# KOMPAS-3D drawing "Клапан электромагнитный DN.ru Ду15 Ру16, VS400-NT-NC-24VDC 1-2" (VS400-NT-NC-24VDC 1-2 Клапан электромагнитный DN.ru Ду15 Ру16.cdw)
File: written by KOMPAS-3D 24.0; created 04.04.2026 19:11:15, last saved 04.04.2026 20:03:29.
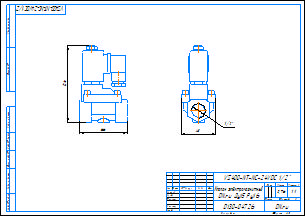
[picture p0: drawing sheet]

Document properties: c3d_UniqueCompID: ef56311e-7521-43dc-8291-0e6108b3d81d; Обозначение: VS400-ET-NC-220VAC 1-2; Наименование: Клапан электромагнитный DN.ru Ду15 Ру16; Автор: artio; Класс точности: c; Знак неуказанной шероховатости: Шероховатость не задана; Рассекать на разрезах: Да; c3d_UniqueCompID: ef56311e-7521-43dc-8291-0e6108b3d81d; Обозначение: VS400-ET-NC-220VAC 3-8; Наименование: Клапан электромагнитный DN.ru Ду10 Ру16; Автор: artio; Класс точности: c; Знак неуказанной шероховатости: Шероховатость не задана; Рассекать на разрезах: Да; Автор: artio; Форматы листов документа: A3; Полное имя файла: VS400-NT-NC-24VDC 1-2 Клапан электромагнитный DN.ru Ду15 Ру16.m3d; Масса: 0.759; Наименование: Клапан электромагнитный DN.ru Ду15 Ру16; Количество листов документа: 1; Примечание: D130-04726

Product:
- Body: Тело 1  | qty 1
    Масса: 1.030062
- Part/product: Клапан электромагнитный DN.ru Ду15 Ру16  | designation VS400-NT-NC-24VDC 1-2
    Масса: 0.759
    Раздел спецификации: Прочие изделия
    Примечание: D130-04726
    additional columns: ef56311e-7521-43dc-8291-0e6108b3d81d; VS400-ET-NC-220VAC 1-2; artio; c; Шероховатость не задана; Да

Views: Вид 1, Спереди, Проекционный вид 2
Referenced files in C:\Users\artio\OneDrive\Рабочий стол\Клапан электромагнитный DN.ru\VS400-ET-NC\VS400-ET-NC-24VDC\: VS400-ET-NC-24VDC 3-8 Клапан электромагнитный DN.ru Ду10 Ру16.m3d
Referenced files in C:\Users\artio\OneDrive\Рабочий стол\Клапан электромагнитный DN.ru\VS400-NT-NC\VS400-NT-NC-24VDC\: VS400-NT-NC-24VDC 1-2 Клапан электромагнитный DN.ru Ду15 Ру16.m3d
Referenced files in C:\Users\artio\OneDrive\Рабочий стол\Клапан электромагнитный DN.ru\VS400-ET-NC\: VS400-ET-NC-24VDC 3-8 Клапан электромагнитный DN.ru Ду10 Ру16.cdw
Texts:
  VS400-NT-NC-24VDC 1-2
  Клапан электромагнитный
  DN.ru Ду15 Ру16
  VS400-NT-NC-24VDC 1/2"
  VS400-NT-NC-24VDC 1/2"-
  Клапан электромагнитный DN.ru Ду15 Ру16
  VS400-NT-NC-24VDC 1-2 Клапан электромагнитный DN.ru Ду15 Ру16
Dimensions and other numbers on the sheet: 0; 3; 2; 4; 48; 1/2"; 66; 106; 1:1; 1; 0,76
